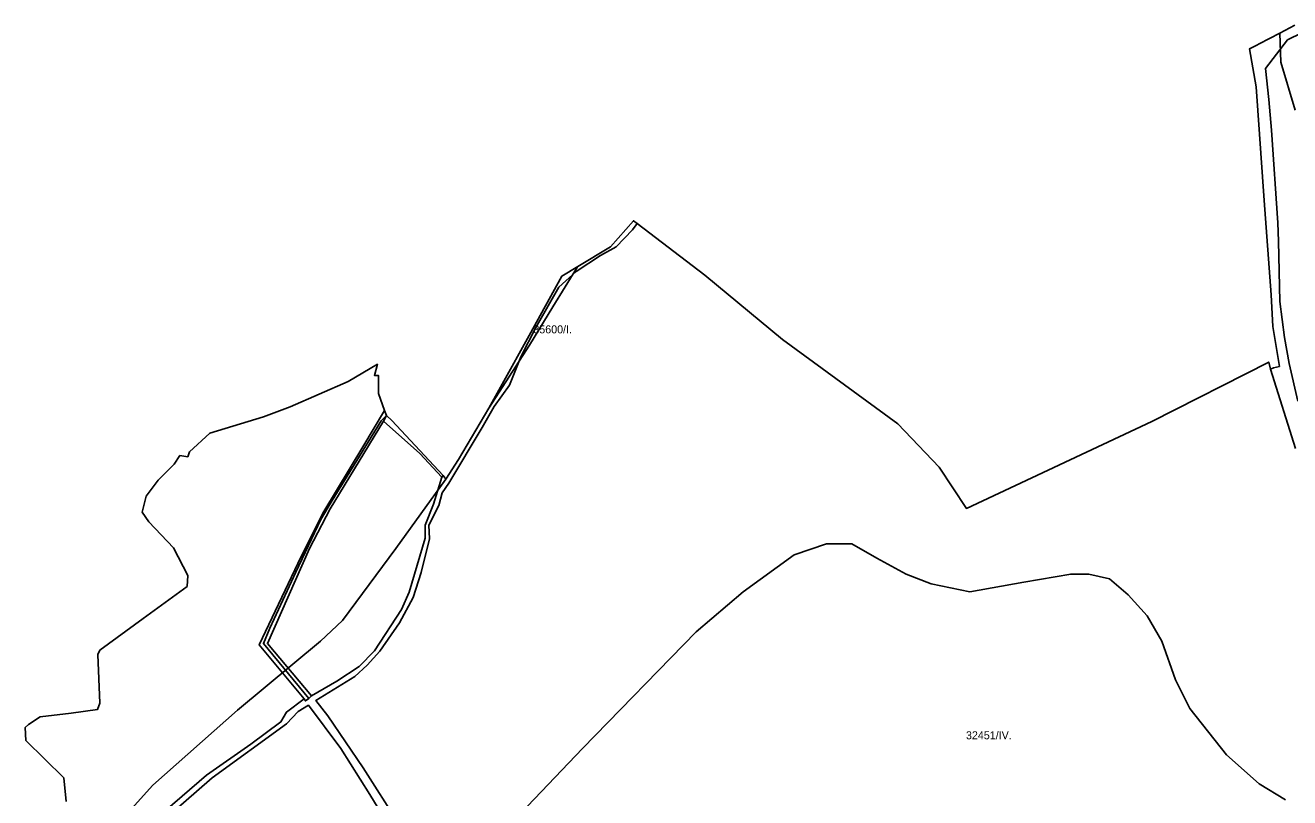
# Model space of a CAD drawing. Extents: x -532083 to -529270, y -1180561 to -1176456.
# Drawn here: x -531821 to -531031, y -1177342 to -1176859 of the extents above; entities that cross this region are included whole.
import ezdxf

# ---------------------------------------------------------------- set-up
doc = ezdxf.new("R2010")
doc.units = 0
for name, color, linetype in [('95560013', 7, 'Continuous'), ('95610013', 7, 'Continuous'), ('95660013', 7, 'Continuous')]:
    doc.layers.add(name, color=color, linetype=linetype)

msp = doc.modelspace()

# ---------------------------------------------------------------- linework, layer by layer
at = {"layer": '95560013'}
for points in [[(-531026.1123, -1177093.83845), (-531031.6673, -1177070.43545), (-531034.4513, -1177054.14045), (-531037.4833, -1177031.60245), (-531038.3473, -1176993.99745), (-531038.7053, -1176982.38145), (-531042.6503, -1176924.53045), (-531044.2603, -1176905.46045), (-531046.3343, -1176886.09745), (-531032.6033, -1176868.07145), (-531014.2283, -1176859.15945)], [(-531588.0313, -1177358.07445), (-531610.2983, -1177323.08245), (-531632.4103, -1177290.47945), (-531639.9723, -1177280.99745), (-531615.5293, -1177265.96745), (-531607.7663, -1177258.98545), (-531600.0023, -1177250.12445), (-531587.6883, -1177232.40145), (-531579.1223, -1177216.55845), (-531574.0353, -1177200.98345), (-531568.9493, -1177180.03845), (-531569.2163, -1177171.44545), (-531563.0593, -1177159.09345), (-531560.9183, -1177151.30545), (-531556.7733, -1177145.08145), (-531535.9823, -1177110.44645), (-531528.4753, -1177097.24345), (-531518.9743, -1177083.95045), (-531511.7233, -1177066.14345), (-531502.4713, -1177047.83445), (-531487.9693, -1177022.75345), (-531477.2173, -1177012.97145), (-531461.9653, -1177002.93945), (-531452.2133, -1176997.42145), (-531441.9623, -1176986.88745), (-531439.0263, -1176982.78945), (-531396.8733, -1177015.10445), (-531348.2533, -1177055.29145), (-531276.2623, -1177108.10145), (-531250.3813, -1177135.17245), (-531233.3493, -1177160.91345), (-531117.3773, -1177106.63945), (-531044.3503, -1177069.52945), (-531043.1993, -1177073.95245), (-531027.6233, -1177123.57445)], [(-531795.8883, -1177344.11545), (-531797.3733, -1177329.40945), (-531821.1253, -1177305.95345), (-531821.4973, -1177297.94945), (-531819.4153, -1177295.94345), (-531812.1673, -1177291.14145), (-531792.8843, -1177288.94645), (-531776.3363, -1177286.61445), (-531774.9683, -1177282.63545), (-531776.0623, -1177252.17945), (-531774.8313, -1177249.57245), (-531747.7323, -1177229.84945), (-531720.3843, -1177209.64945), (-531719.8403, -1177202.96145), (-531728.9563, -1177185.49045), (-531744.3303, -1177169.38545), (-531748.4013, -1177163.37145), (-531746.0073, -1177153.31445), (-531738.3753, -1177143.25745), (-531728.3503, -1177133.34945), (-531724.9083, -1177127.94645), (-531719.9703, -1177128.69645), (-531718.9223, -1177125.54445), (-531706.2033, -1177113.83545), (-531672.5353, -1177103.62845), (-531656.0553, -1177097.53445), (-531619.7393, -1177081.57245), (-531601.3933, -1177070.86845), (-531603.3003, -1177077.77845), (-531600.7993, -1177077.77845), (-531600.7993, -1177089.18445), (-531596.9333, -1177099.67845), (-531610.5633, -1177122.45345), (-531634.9843, -1177162.90545), (-531649.0903, -1177190.90745), (-531675.3203, -1177246.13845), (-531647.2753, -1177279.91745), (-531658.1673, -1177288.18545), (-531661.7003, -1177294.38745), (-531680.5413, -1177308.26645), (-531708.2143, -1177327.75645), (-531734.1213, -1177349.90345)]]:
    msp.add_lwpolyline(points, dxfattribs=at)
msp.add_lwpolyline([(-531626.7733, -1177268.92145), (-531642.5713, -1177278.15345), (-531670.2203, -1177245.44145), (-531643.9063, -1177185.94545), (-531631.0563, -1177161.24045), (-531597.5933, -1177106.46045), (-531574.8383, -1177126.60045), (-531561.1853, -1177141.36945), (-531566.2723, -1177158.28645), (-531571.6263, -1177171.44445), (-531571.6263, -1177179.50045), (-531581.5313, -1177213.33545), (-531586.3503, -1177224.07745), (-531603.2153, -1177249.85545), (-531612.8523, -1177259.79145)], close=True, dxfattribs=at)
at = {"layer": '95610013'}
for points in [[(-531629.7423, -1177155.98345), (-531636.7733, -1177167.90245), (-531652.4443, -1177200.81145), (-531668.7433, -1177235.81645), (-531672.7193, -1177245.29845), (-531644.3113, -1177279.68245), (-531646.4453, -1177281.28845), (-531647.2753, -1177279.91745), (-531675.3203, -1177246.13845), (-531649.0903, -1177190.90745), (-531634.9843, -1177162.90545), (-531610.5633, -1177122.45345), (-531596.9333, -1177099.67845), (-531595.6893, -1177102.84145), (-531599.1083, -1177106.17245), (-531612.5233, -1177128.26545)], [(-531597.5933, -1177106.46045), (-531631.0563, -1177161.24045), (-531643.9063, -1177185.94545), (-531670.2203, -1177245.44145), (-531642.5713, -1177278.15345), (-531644.3113, -1177279.68245), (-531672.7193, -1177245.29845), (-531668.7433, -1177235.81645), (-531652.4443, -1177200.81145), (-531636.7733, -1177167.90245), (-531629.7423, -1177155.98345), (-531612.5233, -1177128.26545), (-531599.1083, -1177106.17245), (-531595.6893, -1177102.84145)], [(-531574.8383, -1177126.60045), (-531597.5933, -1177106.46045), (-531595.6893, -1177102.84145), (-531592.3493, -1177105.93345), (-531560.3683, -1177140.46345), (-531561.1853, -1177141.36945)]]:
    msp.add_lwpolyline(points, close=True, dxfattribs=at)
msp.add_lwpolyline([(-531730.7163, -1177351.93545), (-531704.7753, -1177329.25145), (-531658.2163, -1177295.66945), (-531650.8993, -1177287.88645), (-531644.5783, -1177283.96445), (-531624.2823, -1177311.06845), (-531606.2113, -1177339.70845), (-531571.1533, -1177396.98845)], dxfattribs=at)
at = {"layer": '95660013'}
for points in [[(-531027.8753, -1176912.00045), (-531036.8123, -1176882.00045), (-531037.3783, -1176863.89245), (-531027.9683, -1176858.99445)], [(-531774.3123, -1177370.00045), (-531741.8753, -1177334.00045), (-531688.8753, -1177287.00045), (-531637.0003, -1177244.00045), (-531623.3123, -1177231.00045), (-531589.8753, -1177186.00045), (-531558.5703, -1177142.65345), (-531550.7363, -1177130.34845), (-531531.7233, -1177098.20045), (-531506.3123, -1177059.00045), (-531491.8753, -1177035.00045), (-531476.3753, -1177010.00045), (-531476.2313, -1177009.76545), (-531455.6713, -1176997.44545), (-531441.4213, -1176981.10745), (-531439.0263, -1176982.78945), (-531396.8733, -1177015.10445), (-531348.2533, -1177055.29145), (-531276.2623, -1177108.10145), (-531250.3813, -1177135.17245), (-531233.3493, -1177160.91345), (-531117.3773, -1177106.63945), (-531044.3503, -1177069.52945), (-531043.1993, -1177073.95245), (-531041.2833, -1177072.99045), (-531037.6413, -1177072.22145), (-531041.8893, -1177047.18745), (-531042.8733, -1177027.43345), (-531047.1403, -1176968.50045), (-531052.2593, -1176897.41545), (-531056.4423, -1176873.78945), (-531051.8053, -1176871.50845), (-531050.2593, -1176870.59645), (-531037.3783, -1176863.89245), (-531036.8123, -1176882.00045), (-531027.8753, -1176912.00045)], [(-531795.8883, -1177344.11545), (-531797.3733, -1177329.40945), (-531821.1253, -1177305.95345), (-531821.4973, -1177297.94945), (-531819.4153, -1177295.94345), (-531812.1673, -1177291.14145), (-531792.8843, -1177288.94645), (-531776.3363, -1177286.61445), (-531774.9683, -1177282.63545), (-531776.0623, -1177252.17945), (-531774.8313, -1177249.57245), (-531747.7323, -1177229.84945), (-531720.3843, -1177209.64945), (-531719.8403, -1177202.96145), (-531728.9563, -1177185.49045), (-531744.3303, -1177169.38545), (-531748.4013, -1177163.37145), (-531746.0073, -1177153.31445), (-531738.3753, -1177143.25745), (-531728.3503, -1177133.34945), (-531724.9083, -1177127.94645), (-531719.9703, -1177128.69645), (-531718.9223, -1177125.54445), (-531706.2033, -1177113.83545), (-531672.5353, -1177103.62845), (-531656.0553, -1177097.53445), (-531619.7393, -1177081.57245), (-531601.3933, -1177070.86845), (-531603.3003, -1177077.77845), (-531600.7993, -1177077.77845), (-531600.7993, -1177089.18445), (-531596.9333, -1177099.67845), (-531595.6893, -1177102.84145), (-531592.3493, -1177105.93345), (-531560.3683, -1177140.46345), (-531558.5703, -1177142.65345), (-531589.8753, -1177186.00045), (-531623.3123, -1177231.00045), (-531637.0003, -1177244.00045), (-531688.8753, -1177287.00045), (-531741.8753, -1177334.00045), (-531774.3123, -1177370.00045)], [(-531033.8123, -1177343.00045), (-531050.3753, -1177333.00045), (-531070.6873, -1177315.00045), (-531093.6253, -1177286.00045), (-531102.6873, -1177268.00045), (-531111.1873, -1177244.00045), (-531120.3123, -1177228.00045), (-531132.1253, -1177215.00045), (-531143.8753, -1177205.00045), (-531156.8753, -1177202.00045), (-531168.1253, -1177202.00045), (-531197.3753, -1177207.00045), (-531231.1253, -1177213.00045), (-531255.3123, -1177208.00045), (-531271.0003, -1177202.00045), (-531289.3123, -1177192.00045), (-531305.0003, -1177183.00045), (-531320.6873, -1177183.00045), (-531340.8753, -1177190.00045), (-531372.8753, -1177213.00045), (-531402.1253, -1177238.00045), (-531473.3123, -1177311.00045), (-531507.6253, -1177347.00045)], [(-531507.6253, -1177347.00045), (-531473.3123, -1177311.00045), (-531402.1253, -1177238.00045), (-531372.8753, -1177213.00045), (-531340.8753, -1177190.00045), (-531320.6873, -1177183.00045), (-531305.0003, -1177183.00045), (-531289.3123, -1177192.00045), (-531271.0003, -1177202.00045), (-531255.3123, -1177208.00045), (-531231.1253, -1177213.00045), (-531197.3753, -1177207.00045), (-531168.1253, -1177202.00045), (-531156.8753, -1177202.00045), (-531143.8753, -1177205.00045), (-531132.1253, -1177215.00045), (-531120.3123, -1177228.00045), (-531111.1873, -1177244.00045), (-531102.6873, -1177268.00045), (-531093.6253, -1177286.00045), (-531070.6873, -1177315.00045), (-531050.3753, -1177333.00045), (-531033.8123, -1177343.00045)]]:
    msp.add_lwpolyline(points, dxfattribs=at)
msp.add_lwpolyline([(-531506.3123, -1177059.00045), (-531531.7233, -1177098.20045), (-531523.3783, -1177083.38545), (-531506.6773, -1177052.84545), (-531486.1923, -1177015.73445), (-531476.2313, -1177009.76545), (-531476.3753, -1177010.00045), (-531491.8753, -1177035.00045)], close=True, dxfattribs=at)

# ---------------------------------------------------------------- texts
msp.add_text('35600/I.', height=5, rotation=0.00000003, dxfattribs=at).set_placement((-531503.9773, -1177051.53642))
msp.add_text('32451/IV.', height=5, dxfattribs=at).set_placement((-531233.5938, -1177305.23906))

doc.saveas('drawing.dxf')
